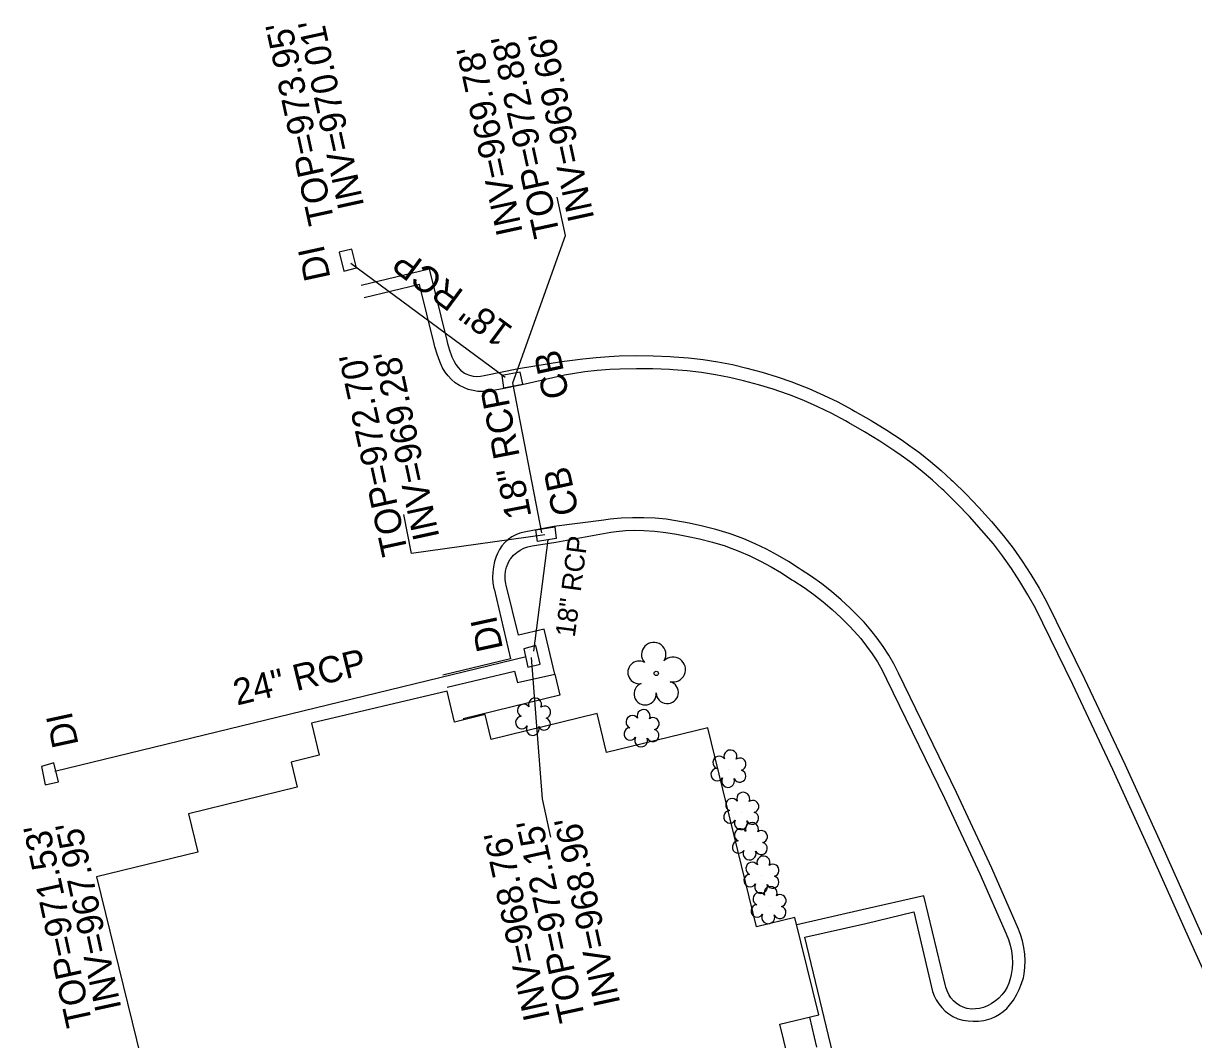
# Model space of a CAD drawing. Extents: x 1611576 to 1617186, y 899279 to 905462.
# Drawn here: x 1615679.7 to 1615858.1, y 904364.8 to 904519.9 of the extents above; entities that cross this region are included whole.
import ezdxf

# ---------------------------------------------------------------- set-up
doc = ezdxf.new("R2010")
doc.units = 0
for name, color, linetype in [('Exist Building', 7, 'Continuous'), ('Exist Other Culture Area Outline', 7, 'Continuous'), ('Exist Roads Curbs', 7, 'Continuous'), ('Exist Roads EOP Other', 7, 'Continuous'), ('Exist Structure Minor Catch Basin', 7, 'Continuous'), ('Exist Structure Minor Catch Basin Leader', 7, 'Continuous'), ('Exist Structure Minor Catch Basin Text', 7, 'Continuous'), ('Exist Structure Minor Catch Basin Top Elevation', 7, 'Continuous'), ('Exist Structure Minor Drop Inlet', 7, 'Continuous'), ('Exist Structure Minor Drop Inlet Leader', 7, 'Continuous'), ('Exist Structure Minor Drop Inlet Text', 7, 'Continuous'), ('Exist Structure Minor Drop Inlet Top Elevation', 7, 'Continuous'), ('Exist Structure Minor Pipes RCP 18 Inch', 7, 'Continuous'), ('Exist Structure Minor Pipes RCP 18 Inch Invert', 7, 'Continuous'), ('Exist Structure Minor Pipes RCP 18 Inch Text', 7, 'Continuous'), ('Exist Structure Minor Pipes RCP 24 Inch', 7, 'Continuous'), ('Exist Structure Minor Pipes RCP 24 Inch Invert', 7, 'Continuous'), ('Exist Structure Minor Pipes RCP 24 Inch Text', 7, 'Continuous'), ('Exist Vegetation Shrub CELL', 7, 'Continuous'), ('Exist Vegetation Tree CELL', 7, 'Continuous')]:
    doc.layers.add(name, color=color, linetype=linetype)

msp = doc.modelspace()

# ---------------------------------------------------------------- linework, layer by layer
at = {"layer": 'Exist Building'}
msp.add_lwpolyline([(1615796.82, 904359.94), (1615795.04, 904367.19), (1615800.95, 904368.63), (1615797.32, 904383.49), (1615791.48, 904382.06), (1615784.05, 904412.43), (1615768.6, 904408.65), (1615767.15, 904414.58), (1615750.99, 904410.63), (1615750.06, 904414.42), (1615745.4, 904413.28), (1615744.28, 904418), (1615723.6, 904413.1), (1615724.75, 904408.23), (1615720.48, 904407.19), (1615721.42, 904403.35), (1615704.83, 904399.3), (1615706.27, 904393.44), (1615690.83, 904389.67), (1615703.65, 904337.25)], dxfattribs=at)
at = {"layer": 'Exist Other Culture Area Outline'}
msp.add_lwpolyline([(1615760.69, 904420.62), (1615761.47, 904417.39), (1615746.75, 904413.76), (1615746.78, 904413.62)], dxfattribs=at)
at = {"layer": 'Exist Roads Curbs'}
for points in [[(1615731.16, 904479.96), (1615741.52, 904482.45), (1615744.25, 904471.48), (1615744.36, 904471.03), (1615744.65, 904470.03), (1615745.02, 904469.01), (1615745.1, 904468.8), (1615745.35, 904468.28), (1615745.63, 904467.82), (1615745.96, 904467.39), (1615746.33, 904466.99), (1615746.73, 904466.65), (1615746.91, 904466.53), (1615747.16, 904466.4), (1615747.69, 904466.2), (1615748.24, 904466.07), (1615748.81, 904466.02), (1615749.37, 904466.05), (1615749.93, 904466.16), (1615755.19, 904467.22), (1615761.73, 904468.29), (1615763.01, 904468.47), (1615765, 904468.7), (1615766.99, 904468.92), (1615768.97, 904469.07), (1615770.54, 904469.14), (1615773.13, 904469.19), (1615775.72, 904469.16), (1615778.29, 904469.05), (1615778.87, 904469.02), (1615781.1, 904468.84), (1615783.34, 904468.58), (1615785.57, 904468.24), (1615787.78, 904467.82), (1615789.99, 904467.3), (1615792.31, 904466.68), (1615794.6, 904465.98), (1615796.87, 904465.2), (1615797.22, 904465.06), (1615799.45, 904464.16), (1615801.67, 904463.17), (1615803.85, 904462.12), (1615805.98, 904460.99), (1615806.53, 904460.68), (1615808.95, 904459.28), (1615811.33, 904457.81), (1615813.66, 904456.28), (1615814.66, 904455.59), (1615816.36, 904454.35), (1615818.02, 904453.04), (1615819.62, 904451.67), (1615821.16, 904450.26), (1615821.4, 904450.02), (1615823.42, 904448.04), (1615825.38, 904446), (1615827.28, 904443.9), (1615829.15, 904441.72), (1615830.6, 904439.8), (1615831.99, 904437.82), (1615833.31, 904435.79), (1615834.56, 904433.73), (1615835.75, 904431.6), (1615841.49, 904419.88), (1615847.63, 904406.89), (1615853.12, 904394.83), (1615859.38, 904380.83)], [(1615744.3, 904418.61), (1615754.58, 904421.03), (1615754.99, 904419.34), (1615760.69, 904420.62), (1615759.08, 904427.47), (1615755.15, 904426.53), (1615753.27, 904434.19), (1615753.22, 904434.4), (1615753.13, 904435.04), (1615753.12, 904435.68), (1615753.2, 904436.32), (1615753.35, 904436.94), (1615753.57, 904437.54), (1615753.87, 904438.11), (1615753.98, 904438.26), (1615754.41, 904438.74), (1615754.9, 904439.16), (1615755.43, 904439.51), (1615756, 904439.8), (1615756.61, 904440.02), (1615757.24, 904440.15), (1615760.88, 904440.75), (1615769.23, 904442.25), (1615770.08, 904442.37), (1615771.47, 904442.51), (1615772.87, 904442.56), (1615774.27, 904442.52), (1615775.95, 904442.4), (1615777.62, 904442.21), (1615779.27, 904441.93), (1615780.81, 904441.65), (1615782.78, 904441.22), (1615784.74, 904440.72), (1615786.66, 904440.15), (1615787.03, 904440.02), (1615788.76, 904439.36), (1615790.44, 904438.63), (1615792.09, 904437.83), (1615793.7, 904436.97), (1615795.28, 904436.04), (1615796.87, 904435.01), (1615797.18, 904434.82), (1615798.72, 904433.81), (1615800.2, 904432.75), (1615801.63, 904431.63), (1615803.01, 904430.45), (1615804.35, 904429.21), (1615805.65, 904427.9), (1615806.37, 904427.14), (1615807.35, 904426.03), (1615808.26, 904424.89), (1615809.11, 904423.69), (1615809.9, 904422.46), (1615810.62, 904421.19), (1615811.3, 904419.85), (1615820.11, 904401.68), (1615825.51, 904390.16), (1615829.55, 904380.96), (1615829.89, 904380.12), (1615830.15, 904379.26), (1615830.34, 904378.38), (1615830.45, 904377.48), (1615830.48, 904376.57), (1615830.43, 904375.67), (1615830.3, 904374.77), (1615830.16, 904374.13), (1615829.95, 904373.46), (1615829.67, 904372.83), (1615829.31, 904372.23), (1615828.89, 904371.67), (1615828.41, 904371.17), (1615827.87, 904370.72), (1615827.29, 904370.34), (1615827.23, 904370.3), (1615826.68, 904370), (1615826.1, 904369.76), (1615825.49, 904369.6), (1615824.86, 904369.52), (1615824.23, 904369.51), (1615823.6, 904369.59), (1615823.52, 904369.6), (1615822.96, 904369.79), (1615822.42, 904370.05), (1615821.93, 904370.39), (1615821.49, 904370.78), (1615821.1, 904371.23), (1615820.78, 904371.73), (1615820.53, 904372.27), (1615820.35, 904372.84), (1615820.31, 904373.03), (1615817, 904386.76), (1615807.59, 904384.63), (1615797.6, 904382.36)], [(1615799.53, 904368.28), (1615800.62, 904363.71)]]:
    msp.add_lwpolyline(points, dxfattribs=at)
at = {"layer": 'Exist Roads EOP Other'}
for points in [[(1615863.88, 904365.98), (1615857.57, 904380.02), (1615851.31, 904394.01), (1615845.82, 904406.05), (1615839.69, 904419.02), (1615833.99, 904430.67), (1615832.84, 904432.72), (1615831.62, 904434.73), (1615830.34, 904436.7), (1615828.98, 904438.63), (1615827.6, 904440.47), (1615825.79, 904442.58), (1615823.92, 904444.64), (1615822, 904446.64), (1615820.02, 904448.59), (1615819.79, 904448.8), (1615818.3, 904450.18), (1615816.75, 904451.5), (1615815.16, 904452.76), (1615813.52, 904453.96), (1615812.55, 904454.62), (1615810.26, 904456.13), (1615807.92, 904457.57), (1615805.55, 904458.95), (1615805.03, 904459.24), (1615802.95, 904460.34), (1615800.83, 904461.37), (1615798.67, 904462.32), (1615796.49, 904463.21), (1615796.19, 904463.32), (1615793.98, 904464.08), (1615791.76, 904464.76), (1615789.5, 904465.37), (1615787.37, 904465.87), (1615785.23, 904466.28), (1615783.08, 904466.61), (1615780.91, 904466.86), (1615778.74, 904467.03), (1615778.2, 904467.06), (1615775.67, 904467.17), (1615773.14, 904467.2), (1615770.6, 904467.15), (1615769.08, 904467.08), (1615767.17, 904466.94), (1615765.27, 904466.72), (1615763.38, 904466.42), (1615762.18, 904466.19), (1615755.73, 904464.72), (1615752.74, 904464.11), (1615750.46, 904463.74), (1615749.71, 904463.7), (1615748.97, 904463.74), (1615748.23, 904463.85), (1615747.51, 904464.04), (1615746.81, 904464.31), (1615746.15, 904464.65), (1615745.53, 904465.05), (1615744.96, 904465.55), (1615744.44, 904466.09), (1615743.98, 904466.69), (1615743.59, 904467.34), (1615743.27, 904468.02), (1615743.16, 904468.31), (1615742.76, 904469.41), (1615742.43, 904470.52), (1615742.31, 904471.01), (1615740.06, 904480.05), (1615731.63, 904478.03)], [(1615803.08, 904362.72), (1615798.82, 904380.47), (1615808.12, 904382.55), (1615815.45, 904384.33), (1615818.31, 904372.21), (1615818.56, 904371.53), (1615818.88, 904370.89), (1615819.27, 904370.28), (1615819.72, 904369.72), (1615820.23, 904369.21), (1615820.8, 904368.76), (1615821.41, 904368.38), (1615822.06, 904368.07), (1615822.16, 904368.03), (1615822.93, 904367.82), (1615823.72, 904367.69), (1615824.52, 904367.64), (1615825.32, 904367.67), (1615826.11, 904367.78), (1615826.56, 904367.88), (1615827.25, 904368.08), (1615827.9, 904368.36), (1615828.53, 904368.71), (1615829.1, 904369.13), (1615829.63, 904369.61), (1615830.07, 904370.11), (1615830.63, 904370.87), (1615831.12, 904371.67), (1615831.54, 904372.51), (1615831.89, 904373.39), (1615832.16, 904374.29), (1615832.29, 904374.86), (1615832.4, 904375.87), (1615832.42, 904376.89), (1615832.37, 904377.9), (1615832.23, 904378.91), (1615832.02, 904379.91), (1615831.73, 904380.88), (1615831.41, 904381.72), (1615827.35, 904390.99), (1615821.94, 904402.55), (1615813.11, 904420.75), (1615812.4, 904422.15), (1615811.63, 904423.51), (1615810.78, 904424.83), (1615809.87, 904426.1), (1615808.9, 904427.33), (1615807.86, 904428.51), (1615807.1, 904429.31), (1615805.76, 904430.66), (1615804.36, 904431.96), (1615802.91, 904433.2), (1615801.41, 904434.37), (1615799.86, 904435.48), (1615798.27, 904436.52), (1615797.95, 904436.72), (1615796.34, 904437.76), (1615794.69, 904438.74), (1615793, 904439.64), (1615791.28, 904440.47), (1615789.52, 904441.23), (1615787.73, 904441.91), (1615787.28, 904442.07), (1615785.28, 904442.67), (1615783.25, 904443.19), (1615781.2, 904443.64), (1615779.14, 904444.01), (1615777.69, 904444.23), (1615775.99, 904444.39), (1615774.27, 904444.47), (1615772.56, 904444.47), (1615770.84, 904444.39), (1615769.13, 904444.23), (1615768.17, 904444.11), (1615760.58, 904443.14), (1615756.04, 904442.28), (1615755.38, 904442.11), (1615754.75, 904441.85), (1615754.15, 904441.53), (1615753.6, 904441.14), (1615753.09, 904440.68), (1615752.65, 904440.17), (1615752.26, 904439.61), (1615751.95, 904439.01), (1615751.77, 904438.57), (1615751.51, 904437.78), (1615751.33, 904436.97), (1615751.23, 904436.15), (1615751.21, 904435.33), (1615751.27, 904434.5), (1615751.41, 904433.69), (1615751.44, 904433.59), (1615753.95, 904422.91), (1615743.63, 904420.46)]]:
    msp.add_lwpolyline(points, dxfattribs=at)
at = {"layer": 'Exist Structure Minor Catch Basin'}
for points in [[(1615752.63, 904466.14), (1615752.87, 904464.3), (1615755.81, 904464.86), (1615755.43, 904466.66), (1615752.63, 904466.14)], [(1615758.08, 904440.83), (1615757.8, 904442.63), (1615760.71, 904443.08), (1615760.92, 904441.28), (1615758.08, 904440.83)]]:
    msp.add_lwpolyline(points, dxfattribs=at)
at = {"layer": 'Exist Structure Minor Catch Basin Leader'}
for points in [[(1615754.3, 904465.06), (1615762.34, 904487.51), (1615761.06, 904493.37)], [(1615759.19, 904441.86), (1615738.84, 904438.98), (1615737.67, 904444.93)]]:
    msp.add_lwpolyline(points, dxfattribs=at)
at = {"layer": 'Exist Structure Minor Drop Inlet'}
for points in [[(1615728.53, 904482.09), (1615730.47, 904482.6), (1615729.75, 904485.43), (1615727.83, 904484.96), (1615728.53, 904482.09)], [(1615756.6, 904421.64), (1615758.47, 904422.1), (1615757.83, 904424.96), (1615755.96, 904424.48), (1615756.6, 904421.64)], [(1615684.32, 904407.06), (1615682.44, 904406.53), (1615682.99, 904403.69), (1615685.01, 904404.19), (1615684.32, 904407.06)]]:
    msp.add_lwpolyline(points, dxfattribs=at)
at = {"layer": 'Exist Structure Minor Drop Inlet Leader'}
msp.add_lwpolyline([(1615757.12, 904423.15), (1615758.78, 904401.59), (1615760.05, 904395.73)], dxfattribs=at)
at = {"layer": 'Exist Structure Minor Pipes RCP 18 Inch'}
for p, q in [((1615753.15, 904465.83), (1615729.6, 904483.25)), ((1615753.15, 904465.83), (1615729.6, 904483.25)), ((1615758.75, 904442.15), (1615754.3, 904465.06)), ((1615758.75, 904442.15), (1615754.3, 904465.06)), ((1615759.66, 904441.1), (1615757.43, 904424.11)), ((1615759.66, 904441.1), (1615757.43, 904424.11))]:
    msp.add_line(p, q, dxfattribs=at)
at = {"layer": 'Exist Structure Minor Pipes RCP 24 Inch'}
msp.add_line((1615756.34, 904423.26), (1615684.48, 904405.75), dxfattribs=at)
msp.add_line((1615756.34, 904423.26), (1615684.48, 904405.75), dxfattribs=at)
at = {"layer": 'Exist Vegetation Shrub CELL'}
for p, q in [((1615757.47, 904413.93), (1615757.47, 904413.93)), ((1615774.01, 904412.17), (1615774.01, 904412.17)), ((1615787.26, 904405.99), (1615787.26, 904405.99)), ((1615789.22, 904399.55), (1615789.22, 904399.55)), ((1615790.53, 904394.93), (1615790.53, 904394.93)), ((1615792.29, 904389.81), (1615792.29, 904389.81)), ((1615793.38, 904385.18), (1615793.38, 904385.18))]:
    msp.add_line(p, q, dxfattribs=at)
for centre, radius, start, end in [((1615757.69, 904415.97), 0.99, 334.8391, 200.4717), ((1615755.98, 904415.05), 0.968, 35.8908, 245.4216), ((1615759.14, 904414.8), 0.929, 284.4567, 126.0861), ((1615774.24, 904414.21), 0.99, 334.8391, 200.4717), ((1615755.67, 904413.22), 0.955, 95.1099, 327.9534), ((1615757.34, 904412.24), 0.984, 151.2797, 21.387), ((1615759.1, 904413), 0.937, 204.9913, 73.4601), ((1615772.53, 904413.3), 0.968, 35.8908, 245.4216), ((1615775.68, 904413.04), 0.929, 284.4567, 126.0861), ((1615772.21, 904411.47), 0.955, 95.1099, 327.9534), ((1615773.88, 904410.49), 0.984, 151.2797, 21.387), ((1615775.65, 904411.24), 0.937, 204.9913, 73.4601), ((1615785.78, 904407.11), 0.968, 35.8908, 245.4216), ((1615787.49, 904408.03), 0.99, 334.8391, 200.4717), ((1615788.93, 904406.86), 0.929, 284.4567, 126.0861), ((1615785.46, 904405.28), 0.955, 95.1099, 327.9534), ((1615788.9, 904405.06), 0.937, 204.9913, 73.4601), ((1615787.13, 904404.3), 0.984, 151.2797, 21.387), ((1615789.44, 904401.59), 0.99, 334.8391, 200.4717), ((1615787.73, 904400.67), 0.968, 35.8908, 245.4216), ((1615790.89, 904400.41), 0.929, 284.4567, 126.0861), ((1615787.42, 904398.84), 0.955, 95.1099, 327.9534), ((1615790.85, 904398.62), 0.937, 204.9913, 73.4601), ((1615789.05, 904396.05), 0.968, 35.8908, 245.4216), ((1615789.09, 904397.86), 0.984, 151.2797, 21.387), ((1615790.76, 904396.97), 0.99, 334.8391, 200.4717), ((1615792.21, 904395.8), 0.929, 284.4567, 126.0861), ((1615788.73, 904394.22), 0.955, 95.1099, 327.9534), ((1615792.17, 904394), 0.937, 204.9913, 73.4601), ((1615790.41, 904393.24), 0.984, 151.2797, 21.387), ((1615790.81, 904390.94), 0.968, 35.8908, 245.4216), ((1615792.52, 904391.86), 0.99, 334.8391, 200.4717), ((1615793.96, 904390.68), 0.929, 284.4567, 126.0861), ((1615790.49, 904389.11), 0.955, 95.1099, 327.9534), ((1615793.93, 904388.89), 0.937, 204.9913, 73.4601), ((1615792.16, 904388.13), 0.984, 151.2797, 21.387), ((1615793.61, 904387.22), 0.99, 334.8391, 200.4717), ((1615791.9, 904386.31), 0.968, 35.8908, 245.4216), ((1615795.05, 904386.05), 0.929, 284.4567, 126.0861), ((1615791.58, 904384.48), 0.955, 95.1099, 327.9534), ((1615795.02, 904384.25), 0.937, 204.9913, 73.4601), ((1615793.25, 904383.5), 0.984, 151.2797, 21.387)]:
    msp.add_arc(centre, radius, start, end, dxfattribs=at)
at = {"layer": 'Exist Vegetation Tree CELL'}
msp.add_line((1615776.18, 904420.71), (1615776.18, 904420.71), dxfattribs=at)
msp.add_circle((1615776.18, 904420.71), 0.326, dxfattribs=at)
for centre, radius, start, end in [((1615775.79, 904423.58), 1.86, 330.1651, 219.7134), ((1615773.57, 904420.86), 1.73, 62.6636, 279.3457), ((1615778.73, 904421.3), 1.9, 257.1011, 134.1999), ((1615774.47, 904417.59), 1.69, 111.5671, 6.231), ((1615777.85, 904417.81), 1.7, 181.2822, 74.56)]:
    msp.add_arc(centre, radius, start, end, dxfattribs=at)

# ---------------------------------------------------------------- texts
at = {"layer": 'Exist Structure Minor Catch Basin Text'}
for p in [(1615762.94, 904463.05), (1615764.39, 904445.25)]:
    msp.add_text('CB', height=4, rotation=102.2667, dxfattribs=at).set_placement(p)
at = {"layer": 'Exist Structure Minor Catch Basin Top Elevation'}
for s, p in [("TOP=972.88'", (1615761.5, 904487.65)), ("TOP=972.70'", (1615738.34, 904439.12))]:
    msp.add_text(s, height=4, rotation=102.2667, dxfattribs=at).set_placement(p)
at = {"layer": 'Exist Structure Minor Drop Inlet Text'}
for p in [(1615726.52, 904481.07), (1615752.83, 904424.51), (1615688.1, 904409.86)]:
    msp.add_text('DI', height=4, rotation=102.2667, dxfattribs=at).set_placement(p)
at = {"layer": 'Exist Structure Minor Drop Inlet Top Elevation'}
for s, p in [("TOP=973.95'", (1615727.13, 904489.61)), ("TOP=971.53'", (1615690.21, 904367.25)), ("TOP=972.15'", (1615765.38, 904367.99))]:
    msp.add_text(s, height=4, rotation=102.2667, dxfattribs=at).set_placement(p)
at = {"layer": 'Exist Structure Minor Pipes RCP 18 Inch Invert'}
for s, p in [("INV=970.01'", (1615731.65, 904492.03)), ("INV=969.66'", (1615766.75, 904490.12)), ("INV=969.78'", (1615755.83, 904488)), ("INV=969.28'", (1615743.13, 904441.52)), ("INV=968.96'", (1615770.71, 904370.38))]:
    msp.add_text(s, height=4, rotation=102.2667, dxfattribs=at).set_placement(p)
at = {"layer": 'Exist Structure Minor Pipes RCP 18 Inch Text'}
for height, rotation, p in [(4, 143.5072, (1615754.52, 904473.39)), (4, 100.9994, (1615757.16, 904444.69)), (3, 82.5271, (1615763.74, 904426.13))]:
    msp.add_text('18" RCP', height=height, rotation=rotation, dxfattribs=at).set_placement(p)
at = {"layer": 'Exist Structure Minor Pipes RCP 24 Inch Invert'}
for s, p in [("INV=967.95'", (1615694.63, 904369.64)), ("INV=968.76'", (1615759.98, 904368.2))]:
    msp.add_text(s, height=4, rotation=102.2667, dxfattribs=at).set_placement(p)
at = {"layer": 'Exist Structure Minor Pipes RCP 24 Inch Text'}
msp.add_text('24" RCP', height=4, rotation=13.6911, dxfattribs=at).set_placement((1615712.23, 904415.8))

doc.saveas('drawing.dxf')
